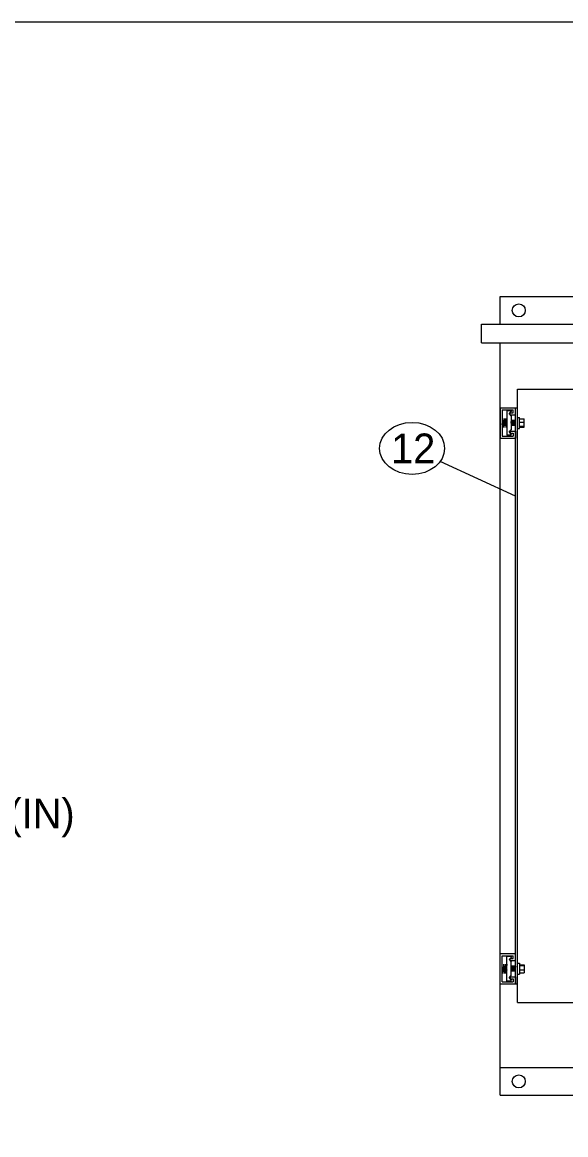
# Model space of a CAD drawing. Extents: x 99862 to 103680, y 99470 to 105076.
# Drawn here: x 101720 to 102012, y 104477 to 105076 of the extents above; entities that cross this region are included whole.
import ezdxf

# ---------------------------------------------------------------- set-up
doc = ezdxf.new("R2010")
doc.units = 0
for name, color, linetype in [('Level 1', 7, 'Continuous'), ('Level 15', 7, 'Continuous'), ('Level 20', 7, 'Continuous'), ('Level 40', 7, 'Continuous')]:
    doc.layers.add(name, color=color, linetype=linetype)

msp = doc.modelspace()

# ---------------------------------------------------------------- linework, layer by layer
at = {"layer": 'Level 1'}
for p, q in [((101985.88, 104547.94), (101985.88, 104877.94)), ((101985.88, 104877.94), (102187.44, 104877.94)), ((101984.79, 104557.94), (101984.79, 104867.94)), ((101985.88, 104547.94), (102187.44, 104547.94))]:
    msp.add_line(p, q, dxfattribs=at)
msp.add_lwpolyline([(99862, 102999.5), (103151, 102999.5), (103151, 105075.5), (99862, 105075.5)], close=True, dxfattribs=at)
at = {"layer": 'Level 15'}
for p, q in [((101966.66, 104912.94), (102386.66, 104912.94)), ((101966.66, 104902.94), (101966.66, 104912.94)), ((101966.66, 104902.94), (102386.66, 104902.94)), ((101984.79, 104820.43), (101944.41, 104839.12))]:
    msp.add_line(p, q, dxfattribs=at)
for centre in [(101986.66, 104920.44), (101986.66, 104505.44)]:
    msp.add_circle(centre, 3.5, dxfattribs=at)
at = {"layer": 'Level 20'}
msp.add_ellipse((101929.26, 104846.13), major_axis=(-17.5, 0), ratio=0.8, dxfattribs=at)
at = {"layer": 'Level 40'}
for p, q in [((101976.66, 104927.94), (102256.66, 104927.94)), ((101976.66, 104912.94), (101976.66, 104927.94)), ((101976.66, 104912.94), (102376.66, 104912.94)), ((101976.66, 104497.94), (101976.66, 104902.94)), ((101976.66, 104867.94), (101976.66, 104851.69)), ((101976.66, 104867.94), (101984.79, 104867.94)), ((101977.76, 104866.84), (101977.76, 104852.78)), ((101977.76, 104866.84), (101983.69, 104866.84)), ((101982.6, 104866.43), (101980.13, 104866.43)), ((101980.13, 104866.43), (101980.13, 104853.19)), ((101981.46, 104864.74), (101982.6, 104865.96)), ((101981.46, 104864.74), (101982.6, 104863.51)), ((101981.97, 104865.28), (101983.69, 104865.28)), ((101981.97, 104864.19), (101981.97, 104865.28)), ((101981.97, 104864.19), (101984.79, 104864.19)), ((101982.6, 104866.43), (101982.6, 104865.96)), ((101983.69, 104865.28), (101983.69, 104866.84)), ((101984.79, 104867.94), (101985.88, 104867.94)), ((101984.79, 104864.19), (101984.79, 104867.94)), ((101977.76, 104858.89), (101978.04, 104862.28)), ((101978.46, 104857.35), (101978.04, 104862.28)), ((101978.46, 104857.35), (101978.88, 104862.28)), ((101979.29, 104857.35), (101978.88, 104862.28)), ((101979.29, 104857.35), (101979.71, 104862.28)), ((101979.45, 104861.17), (101979.45, 104858.46)), ((101980.13, 104861.17), (101979.45, 104861.17)), ((101979.56, 104858.46), (101979.45, 104859.7)), ((101980.13, 104858.46), (101979.45, 104858.46)), ((101979.81, 104858.46), (101979.56, 104861.17)), ((101979.81, 104858.46), (101979.56, 104861.17)), ((101980.13, 104857.35), (101979.71, 104862.28)), ((101980.06, 104858.46), (101979.81, 104861.17)), ((101980.06, 104858.46), (101979.81, 104861.17)), ((101980.13, 104860.42), (101980.06, 104861.17)), ((101982.6, 104863.51), (101982.6, 104856.11)), ((101984.79, 104861.17), (101982.6, 104861.17)), ((101982.8, 104858.46), (101982.6, 104860.54)), ((101984.79, 104858.46), (101982.6, 104858.46)), ((101983.04, 104858.46), (101982.8, 104861.17)), ((101983.29, 104858.46), (101983.04, 104861.17)), ((101983.54, 104858.46), (101983.29, 104861.17)), ((101983.79, 104858.46), (101983.54, 104861.17)), ((101984.04, 104858.46), (101983.79, 104861.17)), ((101984.29, 104858.46), (101984.04, 104861.17)), ((101984.54, 104858.46), (101984.29, 104861.17)), ((101984.79, 104858.46), (101984.54, 104861.17)), ((101985.88, 104862.8), (101987.05, 104862.8)), ((101987.05, 104856.83), (101987.05, 104862.8)), ((101987.05, 104862), (101989.55, 104862)), ((101987.05, 104860.32), (101989.55, 104860.32)), ((101987.05, 104858.13), (101989.55, 104858.13)), ((101989.55, 104857.63), (101989.55, 104862)), ((101977.76, 104852.78), (101983.69, 104852.78)), ((101982.6, 104853.19), (101980.13, 104853.19)), ((101981.46, 104854.89), (101982.6, 104856.11)), ((101981.46, 104854.89), (101982.6, 104853.67)), ((101981.97, 104855.44), (101984.79, 104855.44)), ((101981.97, 104855.44), (101981.97, 104854.34)), ((101981.97, 104854.34), (101983.69, 104854.34)), ((101982.6, 104853.19), (101982.6, 104853.67)), ((101983.69, 104854.34), (101983.69, 104852.78)), ((101984.79, 104855.44), (101984.79, 104851.69)), ((101985.88, 104856.83), (101987.05, 104856.83)), ((101987.05, 104857.63), (101989.55, 104857.63)), ((101976.66, 104851.69), (101984.79, 104851.69)), ((101976.66, 104557.94), (101976.66, 104574.19)), ((101976.66, 104574.19), (101984.79, 104574.19)), ((101977.76, 104559.03), (101977.76, 104573.09)), ((101977.76, 104573.09), (101983.69, 104573.09)), ((101982.6, 104572.68), (101980.13, 104572.68)), ((101980.13, 104559.44), (101980.13, 104572.68)), ((101981.46, 104570.99), (101982.6, 104572.21)), ((101981.46, 104570.99), (101982.6, 104569.76)), ((101981.97, 104571.53), (101983.69, 104571.53)), ((101981.97, 104570.44), (101981.97, 104571.53)), ((101982.6, 104572.68), (101982.6, 104572.21)), ((101983.69, 104571.53), (101983.69, 104573.09)), ((101984.79, 104570.44), (101984.79, 104574.19)), ((101977.76, 104566.99), (101978.04, 104563.6)), ((101978.46, 104568.53), (101978.04, 104563.6)), ((101978.46, 104568.53), (101978.88, 104563.6)), ((101979.29, 104568.53), (101978.88, 104563.6)), ((101979.29, 104568.53), (101979.71, 104563.6)), ((101979.45, 104564.71), (101979.45, 104567.42)), ((101979.56, 104567.42), (101979.45, 104566.18)), ((101980.13, 104567.42), (101979.45, 104567.42)), ((101980.13, 104564.71), (101979.45, 104564.71)), ((101979.81, 104567.42), (101979.56, 104564.71)), ((101979.81, 104567.42), (101979.56, 104564.71)), ((101980.13, 104568.53), (101979.71, 104563.6)), ((101980.06, 104567.42), (101979.81, 104564.71)), ((101980.06, 104567.42), (101979.81, 104564.71)), ((101980.13, 104565.45), (101980.06, 104564.71)), ((101981.97, 104570.44), (101984.79, 104570.44)), ((101982.6, 104562.36), (101982.6, 104569.76)), ((101984.79, 104567.42), (101982.6, 104567.42)), ((101982.8, 104567.42), (101982.6, 104565.34)), ((101984.79, 104564.71), (101982.6, 104564.71)), ((101983.04, 104567.42), (101982.8, 104564.71)), ((101983.29, 104567.42), (101983.04, 104564.71)), ((101983.54, 104567.42), (101983.29, 104564.71)), ((101983.79, 104567.42), (101983.54, 104564.71)), ((101984.04, 104567.42), (101983.79, 104564.71)), ((101984.29, 104567.42), (101984.04, 104564.71)), ((101984.54, 104567.42), (101984.29, 104564.71)), ((101984.79, 104567.42), (101984.54, 104564.71)), ((101985.88, 104569.05), (101987.05, 104569.05)), ((101987.05, 104569.05), (101987.05, 104563.08)), ((101987.05, 104568.25), (101989.55, 104568.25)), ((101987.05, 104567.74), (101989.55, 104567.74)), ((101987.05, 104565.56), (101989.55, 104565.56)), ((101989.55, 104568.25), (101989.55, 104563.88)), ((101977.76, 104559.03), (101983.69, 104559.03)), ((101982.6, 104559.44), (101980.13, 104559.44)), ((101981.46, 104561.14), (101982.6, 104562.36)), ((101981.46, 104561.14), (101982.6, 104559.92)), ((101981.97, 104561.69), (101984.79, 104561.69)), ((101981.97, 104561.69), (101981.97, 104560.59)), ((101981.97, 104560.59), (101983.69, 104560.59)), ((101982.6, 104559.44), (101982.6, 104559.92)), ((101983.69, 104560.59), (101983.69, 104559.03)), ((101984.79, 104561.69), (101984.79, 104557.94)), ((101985.88, 104563.08), (101987.05, 104563.08)), ((101987.05, 104563.88), (101989.55, 104563.88)), ((101976.66, 104557.94), (101984.79, 104557.94)), ((101984.79, 104557.94), (101985.88, 104557.94)), ((101976.66, 104512.94), (102376.66, 104512.94)), ((101976.66, 104497.94), (102376.66, 104497.94))]:
    msp.add_line(p, q, dxfattribs=at)

# ---------------------------------------------------------------- texts
at = {"layer": 'Level 20'}
for s, p in [('12', (101917.93, 104838.13)), ('13/16" (IN) x 1 5/8" (IN)', (101525.63, 104641.65))]:
    msp.add_text(s, height=16, dxfattribs=at).set_placement(p)

doc.saveas('drawing.dxf')
